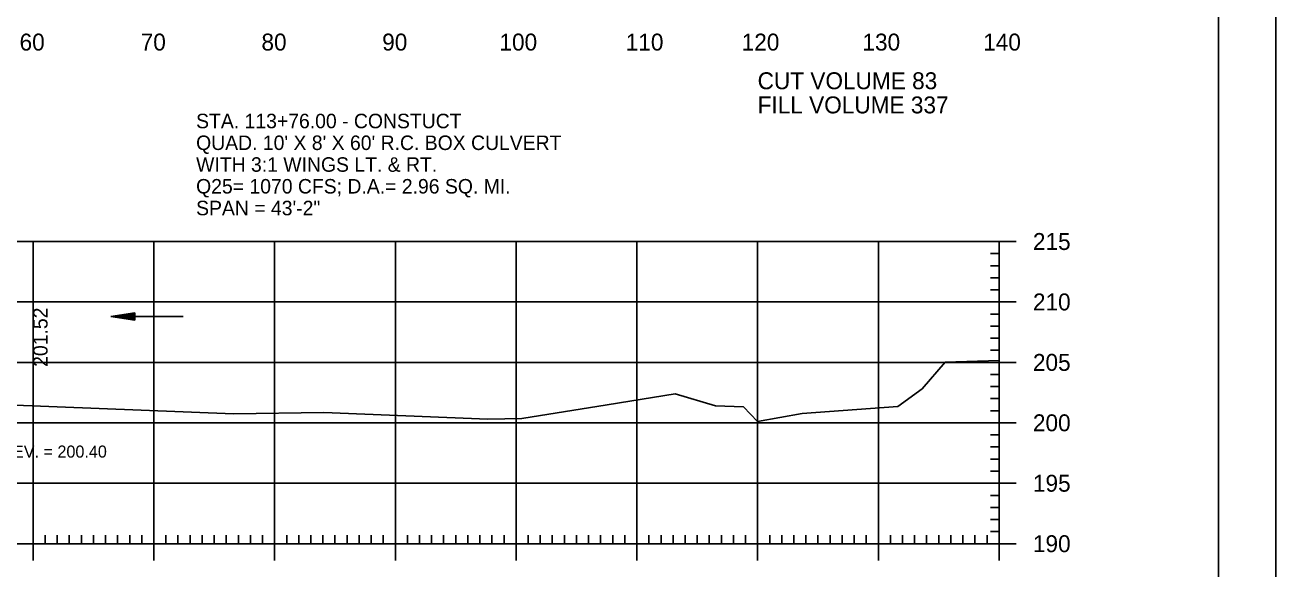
# Model space of a CAD drawing. Extents: x 1312042 to 1371461, y 379929 to 1834241.
# Drawn here: x 1371357.6 to 1371461.2, y 380031.8 to 380076.8 of the extents above; entities that cross this region are included whole.
import ezdxf

# ---------------------------------------------------------------- set-up
doc = ezdxf.new("R2010")
doc.units = 0
for name, color, linetype in [('R_Axis', 7, 'Continuous'), ('R_Axis Annot', 7, 'Continuous'), ('R_Border', 7, 'Continuous'), ('R_Drive', 7, 'Continuous'), ('R_Exist Surface', 7, 'Continuous'), ('R_Grid', 7, 'Continuous'), ('R_No Plot', 7, 'Continuous'), ('R_Water Annot', 7, 'Continuous'), ('R_Xsect Elev', 7, 'Continuous')]:
    doc.layers.add(name, color=color, linetype=linetype)

msp = doc.modelspace()

# ---------------------------------------------------------------- linework, layer by layer
at = {"layer": 'R_Axis'}
for p, q in [((1371439.68, 380058.91), (1371436.88, 380058.91)), ((1371438.28, 380033.91), (1371438.28, 380058.91)), ((1371438.28, 380057.91), (1371437.58, 380057.91)), ((1371438.28, 380056.91), (1371437.58, 380056.91)), ((1371438.28, 380055.91), (1371437.58, 380055.91)), ((1371438.28, 380054.91), (1371437.58, 380054.91)), ((1371439.68, 380053.91), (1371436.88, 380053.91)), ((1371438.28, 380052.91), (1371437.58, 380052.91)), ((1371438.28, 380051.91), (1371437.58, 380051.91)), ((1371438.28, 380050.91), (1371437.58, 380050.91)), ((1371438.28, 380049.91), (1371437.58, 380049.91)), ((1371439.68, 380048.91), (1371436.88, 380048.91)), ((1371438.28, 380047.91), (1371437.58, 380047.91)), ((1371438.28, 380046.91), (1371437.58, 380046.91)), ((1371438.28, 380045.91), (1371437.58, 380045.91)), ((1371438.28, 380044.91), (1371437.58, 380044.91)), ((1371439.68, 380043.91), (1371436.88, 380043.91)), ((1371438.28, 380042.91), (1371437.58, 380042.91)), ((1371438.28, 380041.91), (1371437.58, 380041.91)), ((1371438.28, 380040.91), (1371437.58, 380040.91)), ((1371438.28, 380039.91), (1371437.58, 380039.91)), ((1371439.68, 380038.91), (1371436.88, 380038.91)), ((1371438.28, 380037.91), (1371437.58, 380037.91)), ((1371438.28, 380036.91), (1371437.58, 380036.91)), ((1371358.28, 380032.51), (1371358.28, 380035.31)), ((1371368.28, 380032.51), (1371368.28, 380035.31)), ((1371378.28, 380032.51), (1371378.28, 380035.31)), ((1371388.28, 380032.51), (1371388.28, 380035.31)), ((1371398.28, 380032.51), (1371398.28, 380035.31)), ((1371408.28, 380032.51), (1371408.28, 380035.31)), ((1371418.28, 380032.51), (1371418.28, 380035.31)), ((1371428.28, 380032.51), (1371428.28, 380035.31)), ((1371438.28, 380035.91), (1371437.58, 380035.91)), ((1371438.28, 380032.51), (1371438.28, 380035.31)), ((1371359.28, 380033.91), (1371359.28, 380034.61)), ((1371360.28, 380033.91), (1371360.28, 380034.61)), ((1371361.28, 380033.91), (1371361.28, 380034.61)), ((1371362.28, 380033.91), (1371362.28, 380034.61)), ((1371363.28, 380033.91), (1371363.28, 380034.61)), ((1371364.28, 380033.91), (1371364.28, 380034.61)), ((1371365.28, 380033.91), (1371365.28, 380034.61)), ((1371366.28, 380033.91), (1371366.28, 380034.61)), ((1371367.28, 380033.91), (1371367.28, 380034.61)), ((1371369.28, 380033.91), (1371369.28, 380034.61)), ((1371370.28, 380033.91), (1371370.28, 380034.61)), ((1371371.28, 380033.91), (1371371.28, 380034.61)), ((1371372.28, 380033.91), (1371372.28, 380034.61)), ((1371373.28, 380033.91), (1371373.28, 380034.61)), ((1371374.28, 380033.91), (1371374.28, 380034.61)), ((1371375.28, 380033.91), (1371375.28, 380034.61)), ((1371376.28, 380033.91), (1371376.28, 380034.61)), ((1371377.28, 380033.91), (1371377.28, 380034.61)), ((1371379.28, 380033.91), (1371379.28, 380034.61)), ((1371380.28, 380033.91), (1371380.28, 380034.61)), ((1371381.28, 380033.91), (1371381.28, 380034.61)), ((1371382.28, 380033.91), (1371382.28, 380034.61)), ((1371383.28, 380033.91), (1371383.28, 380034.61)), ((1371384.28, 380033.91), (1371384.28, 380034.61)), ((1371385.28, 380033.91), (1371385.28, 380034.61)), ((1371386.28, 380033.91), (1371386.28, 380034.61)), ((1371387.28, 380033.91), (1371387.28, 380034.61)), ((1371389.28, 380033.91), (1371389.28, 380034.61)), ((1371390.28, 380033.91), (1371390.28, 380034.61)), ((1371391.28, 380033.91), (1371391.28, 380034.61)), ((1371392.28, 380033.91), (1371392.28, 380034.61)), ((1371393.28, 380033.91), (1371393.28, 380034.61)), ((1371394.28, 380033.91), (1371394.28, 380034.61)), ((1371395.28, 380033.91), (1371395.28, 380034.61)), ((1371396.28, 380033.91), (1371396.28, 380034.61)), ((1371397.28, 380033.91), (1371397.28, 380034.61)), ((1371399.28, 380033.91), (1371399.28, 380034.61)), ((1371400.28, 380033.91), (1371400.28, 380034.61)), ((1371401.28, 380033.91), (1371401.28, 380034.61)), ((1371402.28, 380033.91), (1371402.28, 380034.61)), ((1371403.28, 380033.91), (1371403.28, 380034.61)), ((1371404.28, 380033.91), (1371404.28, 380034.61)), ((1371405.28, 380033.91), (1371405.28, 380034.61)), ((1371406.28, 380033.91), (1371406.28, 380034.61)), ((1371407.28, 380033.91), (1371407.28, 380034.61)), ((1371409.28, 380033.91), (1371409.28, 380034.61)), ((1371410.28, 380033.91), (1371410.28, 380034.61)), ((1371411.28, 380033.91), (1371411.28, 380034.61)), ((1371412.28, 380033.91), (1371412.28, 380034.61)), ((1371413.28, 380033.91), (1371413.28, 380034.61)), ((1371414.28, 380033.91), (1371414.28, 380034.61)), ((1371415.28, 380033.91), (1371415.28, 380034.61)), ((1371416.28, 380033.91), (1371416.28, 380034.61)), ((1371417.28, 380033.91), (1371417.28, 380034.61)), ((1371419.28, 380033.91), (1371419.28, 380034.61)), ((1371420.28, 380033.91), (1371420.28, 380034.61)), ((1371421.28, 380033.91), (1371421.28, 380034.61)), ((1371422.28, 380033.91), (1371422.28, 380034.61)), ((1371423.28, 380033.91), (1371423.28, 380034.61)), ((1371424.28, 380033.91), (1371424.28, 380034.61)), ((1371425.28, 380033.91), (1371425.28, 380034.61)), ((1371426.28, 380033.91), (1371426.28, 380034.61)), ((1371427.28, 380033.91), (1371427.28, 380034.61)), ((1371429.28, 380033.91), (1371429.28, 380034.61)), ((1371430.28, 380033.91), (1371430.28, 380034.61)), ((1371431.28, 380033.91), (1371431.28, 380034.61)), ((1371432.28, 380033.91), (1371432.28, 380034.61)), ((1371433.28, 380033.91), (1371433.28, 380034.61)), ((1371434.28, 380033.91), (1371434.28, 380034.61)), ((1371435.28, 380033.91), (1371435.28, 380034.61)), ((1371436.28, 380033.91), (1371436.28, 380034.61)), ((1371437.28, 380033.91), (1371437.28, 380034.61)), ((1371438.28, 380034.91), (1371437.58, 380034.91)), ((1371158.28, 380033.91), (1371438.28, 380033.91)), ((1371439.68, 380033.91), (1371436.88, 380033.91))]:
    msp.add_line(p, q, dxfattribs=at)
at = {"layer": 'R_Border'}
msp.add_line((1371456.46, 379932.91), (1371456.46, 380138.37), dxfattribs=at)
at = {"layer": 'R_Exist Surface'}
msp.add_lwpolyline([(1371356.11, 380045.39), (1371374.89, 380044.65), (1371382.37, 380044.75), (1371395.93, 380044.21), (1371398.75, 380044.27), (1371405.82, 380045.4), (1371411.44, 380046.3), (1371414.79, 380045.32), (1371417.1, 380045.24), (1371418.28, 380044.03), (1371421.96, 380044.67), (1371429.89, 380045.26), (1371431.9, 380046.73), (1371433.82, 380048.93), (1371438.28, 380049.06)], dxfattribs=at)
at = {"layer": 'R_Grid'}
for p, q in [((1371158.28, 380058.91), (1371438.28, 380058.91)), ((1371358.28, 380033.91), (1371358.28, 380058.91)), ((1371368.28, 380033.91), (1371368.28, 380058.91)), ((1371378.28, 380033.91), (1371378.28, 380058.91)), ((1371388.28, 380033.91), (1371388.28, 380058.91)), ((1371398.28, 380033.91), (1371398.28, 380058.91)), ((1371408.28, 380033.91), (1371408.28, 380058.91)), ((1371418.28, 380033.91), (1371418.28, 380058.91)), ((1371428.28, 380033.91), (1371428.28, 380058.91)), ((1371438.28, 380033.91), (1371438.28, 380058.91)), ((1371158.28, 380053.91), (1371438.28, 380053.91)), ((1371158.28, 380048.91), (1371438.28, 380048.91)), ((1371158.28, 380043.91), (1371438.28, 380043.91)), ((1371158.28, 380038.91), (1371438.28, 380038.91)), ((1371158.28, 380033.91), (1371438.28, 380033.91))]:
    msp.add_line(p, q, dxfattribs=at)
at = {"layer": 'R_No Plot'}
for points in [[(1371127.87, 380142.26), (1371461.21, 380142.26), (1371461.21, 379928.93), (1371127.87, 379928.93)], [(1371374.2, 380138.37), (1371374.2, 380128.49), (1371409.93, 380128.49), (1371409.93, 380125.57), (1371433.13, 380125.57), (1371433.13, 380101.24), (1371456.46, 380101.24), (1371456.46, 379932.91), (1371140.28, 379932.91), (1371140.28, 380138.37)]]:
    msp.add_lwpolyline(points, close=True, dxfattribs=at)
at = {"layer": 'R_Water Annot'}
for p, q in [((1371366.71, 380053), (1371364.71, 380052.7)), ((1371366.71, 380052.95), (1371365.04, 380052.7)), ((1371366.71, 380052.9), (1371365.39, 380052.7)), ((1371366.71, 380052.85), (1371365.72, 380052.7)), ((1371366.71, 380052.8), (1371366.06, 380052.7)), ((1371366.71, 380052.4), (1371366.71, 380053)), ((1371370.71, 380052.7), (1371364.71, 380052.7)), ((1371366.71, 380052.4), (1371364.71, 380052.7)), ((1371366.71, 380052.45), (1371365.04, 380052.7)), ((1371366.71, 380052.5), (1371365.39, 380052.7)), ((1371366.71, 380052.55), (1371365.72, 380052.7)), ((1371366.71, 380052.6), (1371366.06, 380052.7)), ((1371366.71, 380052.75), (1371366.39, 380052.7)), ((1371366.71, 380052.65), (1371366.39, 380052.7))]:
    msp.add_line(p, q, dxfattribs=at)

# ---------------------------------------------------------------- texts
at = {"layer": 'R_Axis Annot'}
for s, height, p in [('60', 1.4, (1371357.16, 380074.71)), ('70', 1.4, (1371367.19, 380074.71)), ('80', 1.4, (1371377.19, 380074.71)), ('90', 1.4, (1371387.19, 380074.71)), ('100', 1.4, (1371396.9, 380074.71)), ('110', 1.4, (1371407.36, 380074.71)), ('120', 1.4, (1371416.96, 380074.71)), ('130', 1.4, (1371426.96, 380074.71)), ('140', 1.4, (1371436.96, 380074.71)), ('CUT VOLUME 83', 1.4, (1371418.28, 380071.51)), ('FILL VOLUME 337', 1.4, (1371418.28, 380069.51)), ('215', 1.4, (1371441.08, 380058.21)), ('210', 1.4, (1371441.08, 380053.21)), ('205', 1.4, (1371441.08, 380048.21)), ('200', 1.4, (1371441.08, 380043.21)), ('F.L. INLET RT. ELEV. = 200.40', 1, (1371345.62, 380041.03)), ('195', 1.4, (1371441.08, 380038.21)), ('190', 1.4, (1371441.08, 380033.21))]:
    msp.add_text(s, height=height, dxfattribs=at).set_placement(p)
at = {"layer": 'R_Drive'}
for s, p in [('STA. 113+76.00 - CONSTUCT', (1371371.78, 380068.28)), ("QUAD. 10' X 8' X 60' R.C. BOX CULVERT", (1371371.78, 380066.48)), ('WITH 3:1 WINGS LT. & RT.', (1371371.78, 380064.68)), ('Q25= 1070 CFS; D.A.= 2.96 SQ. MI.', (1371371.78, 380062.88)), ('SPAN = 43\'-2"', (1371371.78, 380061.08))]:
    msp.add_text(s, height=1.2, dxfattribs=at).set_placement(p)
at = {"layer": 'R_Xsect Elev'}
msp.add_text('201.52', height=1.2, rotation=90, dxfattribs=at).set_placement((1371359.48, 380048.54))

doc.saveas('drawing.dxf')
